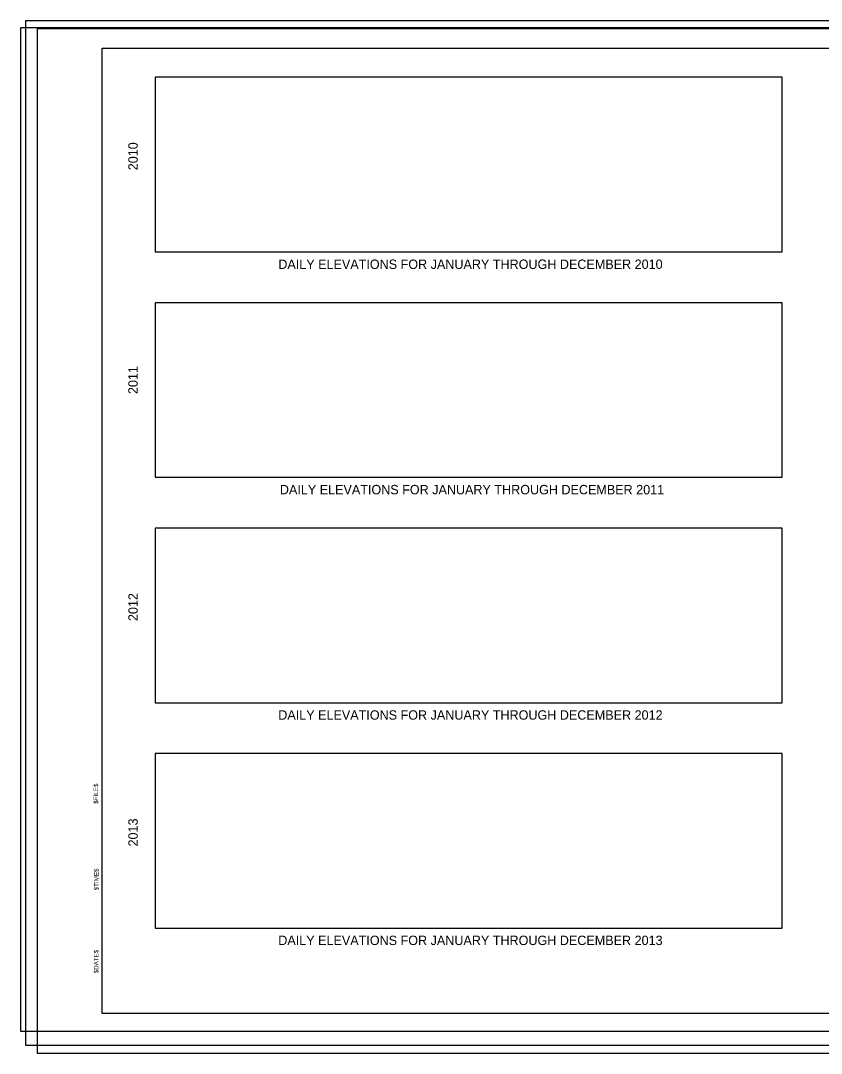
# Model space of a CAD drawing. Extents: x -1063117.9 to -1063075.9, y -253323.6 to -253301.6.
# Drawn here: x -1063117.89 to -1063100.86, y -253323.61 to -253301.63 of the extents above; entities that cross this region are included whole.
import ezdxf

# ---------------------------------------------------------------- set-up
doc = ezdxf.new("R2010")
doc.units = 0
for name, color, linetype in [('border', 7, 'Continuous'), ('Border 2660-Hwy18 - Level 62', 7, 'Continuous'), ('Border 2660-Hwy18 - Level 63', 7, 'Continuous'), ('Dimensions', 7, 'Continuous'), ('Level 62 PDF', 7, 'Continuous'), ('Title Text', 7, 'Continuous')]:
    doc.layers.add(name, color=color, linetype=linetype)

msp = doc.modelspace()

# ---------------------------------------------------------------- linework, layer by layer
at = {"layer": 'border'}
for p, q in [((-1063116.157, -253302.216), (-1063084.146, -253302.216)), ((-1063116.157, -253322.761), (-1063116.157, -253302.216)), ((-1063084.146, -253322.761), (-1063116.157, -253322.761))]:
    msp.add_line(p, q, dxfattribs=at)
at = {"layer": 'Border 2660-Hwy18 - Level 62'}
msp.add_lwpolyline([(-1063117.777, -253301.63), (-1063083.659, -253301.63), (-1063083.659, -253323.44), (-1063117.777, -253323.44)], close=True, dxfattribs=at)
at = {"layer": 'Border 2660-Hwy18 - Level 63'}
msp.add_lwpolyline([(-1063117.888, -253301.773), (-1063083.889, -253301.773), (-1063083.889, -253323.143), (-1063117.888, -253323.143)], close=True, dxfattribs=at)
at = {"layer": 'Dimensions'}
for points in [[(-1063115.028, -253306.552), (-1063101.694, -253306.552), (-1063101.694, -253302.836), (-1063115.028, -253302.836)], [(-1063115.027, -253311.348), (-1063101.694, -253311.348), (-1063101.694, -253307.632), (-1063115.027, -253307.632)], [(-1063115.027, -253316.144), (-1063101.694, -253316.144), (-1063101.694, -253312.428), (-1063115.027, -253312.428)], [(-1063115.027, -253320.94), (-1063101.693, -253320.94), (-1063101.693, -253317.224), (-1063115.027, -253317.224)]]:
    msp.add_lwpolyline(points, close=True, dxfattribs=at)
at = {"layer": 'Level 62 PDF'}
msp.add_lwpolyline([(-1063117.527, -253301.797), (-1063083.409, -253301.797), (-1063083.409, -253323.607), (-1063117.527, -253323.607)], close=True, dxfattribs=at)

# ---------------------------------------------------------------- texts
at = {"layer": 'border'}
for s, p in [('$FILE$', (-1063116.24, -253318.295)), ('$TIME$', (-1063116.23, -253320.136)), ('$DATE$', (-1063116.234, -253321.903))]:
    msp.add_text(s, height=0.096, rotation=89.9999, dxfattribs=at).set_placement(p)
at = {"layer": 'Title Text'}
for s, p in [('2010', (-1063115.399, -253304.814)), ('2011', (-1063115.399, -253309.577)), ('2012', (-1063115.398, -253314.407)), ('2013', (-1063115.398, -253319.204))]:
    msp.add_text(s, height=0.2, rotation=90, dxfattribs=at).set_placement(p)
for s, p in [(' DAILY ELEVATIONS FOR JANUARY THROUGH DECEMBER 2010 ', (-1063112.482, -253306.914)), (' DAILY ELEVATIONS FOR JANUARY THROUGH DECEMBER 2011 ', (-1063112.449, -253311.71)), (' DAILY ELEVATIONS FOR JANUARY THROUGH DECEMBER 2012 ', (-1063112.483, -253316.506)), (' DAILY ELEVATIONS FOR JANUARY THROUGH DECEMBER 2013 ', (-1063112.483, -253321.302))]:
    msp.add_text(s, height=0.2, dxfattribs=at).set_placement(p)

doc.saveas('drawing.dxf')
